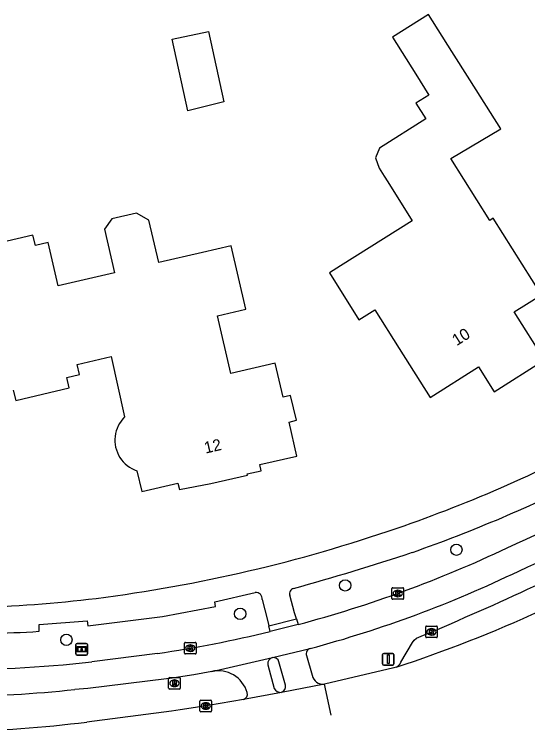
# Model space of a CAD drawing. Extents: x 161354 to 161876, y 382161 to 382804.
# Drawn here: x 161596.3 to 161640.6, y 382163 to 382224.9 of the extents above; entities that cross this region are included whole.
import ezdxf

# ---------------------------------------------------------------- set-up
doc = ezdxf.new("R2010")
doc.units = 0
for name, color, linetype in [('IMGEO_Boom', 7, 'Continuous'), ('IMGEO_Fietspad_gesloten', 7, 'Continuous'), ('IMGEO_Fietspad_open', 7, 'Continuous'), ('IMGEO_Informatiebord', 7, 'Continuous'), ('IMGEO_Kolk', 7, 'Continuous'), ('IMGEO_Pand', 7, 'Continuous'), ('IMGEO_Pand_nummerreeks', 7, 'Continuous'), ('IMGEO_Parkeervlak_gesloten', 7, 'Continuous'), ('IMGEO_Rijbaan_lokaal_gesloten', 7, 'Continuous'), ('IMGEO_Rioolput', 7, 'Continuous'), ('IMGEO_Verkeersbordpaal', 7, 'Continuous'), ('IMGEO_Voetpad_open', 7, 'Continuous')]:
    doc.layers.add(name, color=color, linetype=linetype)

msp = doc.modelspace()

# ---------------------------------------------------------------- linework, layer by layer
at = {"layer": 'IMGEO_Boom'}
for centre in [(161634.464, 382178.675), (161624.869, 382175.601), (161615.807, 382173.143), (161600.809, 382170.903)]:
    msp.add_circle(centre, 0.489, dxfattribs=at)
at = {"layer": 'IMGEO_Fietspad_gesloten'}
for points in [[(161620.807, 382172.222), (161618.406, 382171.615)], [(161618.604, 382169.368), (161621.848, 382170.151)], [(161608.671, 382169.723), (161603.005, 382168.994)], [(161613.35, 382168.179), (161618.604, 382169.368)], [(161613.35, 382168.179), (161611.805, 382167.893), (161609.731, 382167.57), (161609.449, 382167.536), (161602.674, 382166.712), (161601.532, 382166.616)]]:
    msp.add_lwpolyline(points, dxfattribs=at)
for centre, radius, start, end in [((161590.684, 382287.002), 118.402, 294.00068, 300.94195), ((161589.217, 382289.524), 123.534, 294.19262, 300.59138), ((161593.567, 382274.394), 105.741, 284.92819, 295.35244), ((161595.386, 382268.883), 102.217, 285.00366, 295.78007), ((161592.438, 382279.237), 110.71, 278.43128, 283.5654), ((161589.272, 382297.98), 129.715, 270.22249, 276.0772), ((161589.939, 382275.328), 109.328, 270.56918, 276.08702)]:
    msp.add_arc(centre, radius, start, end, dxfattribs=at)
at = {"layer": 'IMGEO_Fietspad_open'}
msp.add_lwpolyline([(161618.183, 382168.756), (161618.75, 382166.701)], dxfattribs=at)
for centre, radius, start, end in [((161618.759, 382168.811), 0.579, 105.54251, 185.40866), ((161613.898, 382165.611), 2.626, 16.30451, 102.05393), ((161615.958, 382166.226), 0.477, 284.90509, 14.88803), ((161619.281, 382166.949), 0.586, 205.02601, 278.85775)]:
    msp.add_arc(centre, radius, start, end, dxfattribs=at)
at = {"layer": 'IMGEO_Informatiebord'}
for p, q in [((161601.637, 382169.684), (161601.637, 382170.484)), ((161601.637, 382170.484), (161601.637, 382169.684)), ((161601.737, 382170.584), (161602.527, 382170.584)), ((161602.527, 382170.584), (161601.737, 382170.584)), ((161602.627, 382170.484), (161602.627, 382169.684)), ((161602.627, 382169.684), (161602.627, 382170.484)), ((161602.527, 382169.584), (161601.737, 382169.584)), ((161601.737, 382169.584), (161602.527, 382169.584))]:
    msp.add_line(p, q, dxfattribs=at)
for points in [[(161601.738, 382170.316), (161602.526, 382170.316), (161602.526, 382169.852), (161601.738, 382169.852), (161601.738, 382170.316)], [(161601.803, 382170.251), (161601.803, 382169.917), (161602.078, 382169.917), (161602.079, 382170.13), (161602.183, 382170.131), (161602.184, 382169.917), (161602.461, 382169.917), (161602.461, 382170.251), (161602.185, 382170.251), (161602.185, 382170.171), (161602.079, 382170.171), (161602.079, 382170.251), (161601.803, 382170.251)]]:
    msp.add_lwpolyline(points, dxfattribs=at)
for centre, start, end in [((161601.737, 382170.484), 90, 180), ((161601.737, 382170.484), 90, 180), ((161602.527, 382170.484), 0, 90), ((161602.527, 382170.484), 360, 90), ((161601.737, 382169.684), 180, 270), ((161601.737, 382169.684), 180, 270), ((161602.527, 382169.684), 270, 0), ((161602.527, 382169.684), 270, 0)]:
    msp.add_arc(centre, 0.1, start, end, dxfattribs=at)
at = {"layer": 'IMGEO_Kolk'}
for p, q in [((161628.909, 382174.472), (161628.909, 382175.324)), ((161628.984, 382175.398), (161629.836, 382175.398)), ((161629.397, 382175.178), (161629.422, 382175.178)), ((161629.91, 382175.324), (161629.91, 382174.472)), ((161629.836, 382174.398), (161628.984, 382174.398)), ((161629.42, 382174.618), (161629.395, 382174.618)), ((161631.816, 382171.163), (161631.816, 382172.015)), ((161631.891, 382172.089), (161632.743, 382172.089)), ((161632.304, 382171.869), (161632.329, 382171.869)), ((161632.817, 382172.015), (161632.817, 382171.163)), ((161632.327, 382171.309), (161632.302, 382171.309)), ((161611.003, 382169.754), (161611.003, 382170.606)), ((161611.078, 382170.68), (161611.93, 382170.68)), ((161612.004, 382170.606), (161612.004, 382169.754)), ((161632.743, 382171.089), (161631.891, 382171.089)), ((161611.491, 382170.46), (161611.516, 382170.46)), ((161611.93, 382169.68), (161611.078, 382169.68)), ((161611.514, 382169.9), (161611.489, 382169.9)), ((161612.415, 382165.695), (161613.267, 382165.695)), ((161612.34, 382164.769), (161612.34, 382165.621)), ((161612.828, 382165.475), (161612.853, 382165.475)), ((161613.341, 382165.621), (161613.341, 382164.769)), ((161613.267, 382164.695), (161612.415, 382164.695)), ((161612.851, 382164.915), (161612.826, 382164.915))]:
    msp.add_line(p, q, dxfattribs=at)
for points in [[(161628.909, 382174.472), (161628.909, 382175.324)], [(161628.984, 382175.398), (161629.836, 382175.398)], [(161629.23, 382175.098), (161629.353, 382175.098), (161629.353, 382174.947), (161629.483, 382175.098), (161629.647, 382175.098), (161629.501, 382174.947), (161629.654, 382174.698), (161629.502, 382174.698), (161629.417, 382174.862), (161629.353, 382174.795), (161629.353, 382174.698), (161629.23, 382174.698), (161629.23, 382175.098)], [(161629.91, 382175.324), (161629.91, 382174.472)], [(161629.836, 382174.398), (161628.984, 382174.398)], [(161631.816, 382171.163), (161631.816, 382172.015)], [(161631.891, 382172.089), (161632.743, 382172.089)], [(161632.817, 382172.015), (161632.817, 382171.163)], [(161632.137, 382171.789), (161632.26, 382171.789), (161632.26, 382171.638), (161632.39, 382171.789), (161632.554, 382171.789), (161632.408, 382171.638), (161632.561, 382171.389), (161632.409, 382171.389), (161632.324, 382171.553), (161632.26, 382171.486), (161632.26, 382171.389), (161632.137, 382171.389), (161632.137, 382171.789)], [(161611.003, 382169.754), (161611.003, 382170.606)], [(161611.078, 382170.68), (161611.93, 382170.68)], [(161612.004, 382170.606), (161612.004, 382169.754)], [(161632.743, 382171.089), (161631.891, 382171.089)], [(161611.324, 382170.38), (161611.447, 382170.38), (161611.447, 382170.229), (161611.577, 382170.38), (161611.741, 382170.38), (161611.595, 382170.229), (161611.748, 382169.98), (161611.596, 382169.98), (161611.511, 382170.144), (161611.447, 382170.077), (161611.447, 382169.98), (161611.324, 382169.98), (161611.324, 382170.38)], [(161611.93, 382169.68), (161611.078, 382169.68)], [(161612.415, 382165.695), (161613.267, 382165.695)], [(161612.34, 382164.769), (161612.34, 382165.621)], [(161612.661, 382165.395), (161612.784, 382165.395), (161612.784, 382165.244), (161612.914, 382165.395), (161613.078, 382165.395), (161612.932, 382165.244), (161613.085, 382164.995), (161612.933, 382164.995), (161612.848, 382165.159), (161612.784, 382165.092), (161612.784, 382164.995), (161612.661, 382164.995), (161612.661, 382165.395)], [(161613.341, 382165.621), (161613.341, 382164.769)], [(161613.267, 382164.695), (161612.415, 382164.695)]]:
    msp.add_lwpolyline(points, dxfattribs=at)
for centre, start, end in [((161628.986, 382175.322), 91.55205, 178.44795), ((161628.986, 382175.322), 91.55205, 178.44795), ((161629.834, 382175.322), 1.55205, 88.44795), ((161629.834, 382175.322), 1.55205, 88.44795), ((161628.986, 382174.474), 181.55205, 268.44795), ((161628.986, 382174.474), 181.55205, 268.44795), ((161629.834, 382174.474), 271.55205, 358.44795), ((161629.834, 382174.474), 271.55205, 358.44795), ((161631.893, 382172.013), 91.55205, 178.44795), ((161631.893, 382172.013), 91.55205, 178.44795), ((161632.741, 382172.013), 1.55205, 88.44795), ((161632.741, 382172.013), 1.55205, 88.44795), ((161611.08, 382170.604), 91.55205, 178.44795), ((161611.08, 382170.604), 91.55205, 178.44795), ((161611.928, 382170.604), 1.55205, 88.44795), ((161611.928, 382170.604), 1.55205, 88.44795), ((161631.893, 382171.165), 181.55205, 268.44795), ((161631.893, 382171.165), 181.55205, 268.44795), ((161632.741, 382171.165), 271.55205, 358.44795), ((161632.741, 382171.165), 271.55205, 358.44795), ((161611.08, 382169.756), 181.55205, 268.44795), ((161611.08, 382169.756), 181.55205, 268.44795), ((161611.928, 382169.756), 271.55205, 358.44795), ((161611.928, 382169.756), 271.55205, 358.44795), ((161612.417, 382165.619), 91.55205, 178.44795), ((161612.417, 382165.619), 91.55205, 178.44795), ((161613.265, 382165.619), 1.55205, 88.44795), ((161613.265, 382165.619), 1.55205, 88.44795), ((161612.417, 382164.771), 181.55205, 268.44795), ((161612.417, 382164.771), 181.55205, 268.44795), ((161613.265, 382164.771), 271.55205, 358.44795), ((161613.265, 382164.771), 271.55205, 358.44795)]:
    msp.add_arc(centre, 0.0765, start, end, dxfattribs=at)
for centre, major_axis, ratio, start_param, end_param in [((161629.396, 382174.898), (-0.387, 0.002), 0.722429, 4.712389, 7.853982), ((161629.421, 382174.898), (-0.39, 0.002), 0.717154, 1.570796, 4.712389), ((161632.303, 382171.589), (-0.387, 0.002), 0.722429, 4.712389, 7.853982), ((161632.328, 382171.589), (-0.39, 0.002), 0.717154, 1.570796, 4.712389), ((161611.49, 382170.18), (-0.387, 0.002), 0.722429, 4.712389, 7.853982), ((161611.515, 382170.18), (-0.39, 0.002), 0.717154, 1.570796, 4.712389), ((161612.827, 382165.195), (-0.387, 0.002), 0.722429, 4.712389, 7.853982), ((161612.852, 382165.195), (-0.39, 0.002), 0.717154, 1.570796, 4.712389)]:
    msp.add_ellipse(centre, major_axis=major_axis, ratio=ratio, start_param=start_param, end_param=end_param, dxfattribs=at)
at = {"layer": 'IMGEO_Pand'}
for points in [[(161628.942, 382222.91), (161630.959, 382219.713), (161632.095, 382217.912), (161630.979, 382217.209), (161631.825, 382215.867), (161627.824, 382213.343), (161627.496, 382212.485), (161627.793, 382211.616), (161628.233, 382210.919), (161628.54, 382210.432), (161630.658, 382207.071), (161624.462, 382203.164), (161623.504, 382202.56), (161626.047, 382198.524), (161627.419, 382199.389), (161629.528, 382196.042), (161632.194, 382191.812), (161636.375, 382194.447), (161637.719, 382192.315), (161642.061, 382195.052), (161639.449, 382199.198), (161641.81, 382200.686), (161637.651, 382207.285), (161637.347, 382207.094), (161633.988, 382212.424), (161638.292, 382214.996), (161635.626, 382219.226), (161634.08, 382221.68), (161632.065, 382224.878), (161628.942, 382222.91)], [(161614.403, 382217.316), (161611.289, 382216.544), (161609.951, 382222.728), (161613.088, 382223.392), (161614.403, 382217.316)], [(161608.786, 382203.456), (161607.939, 382207.103), (161606.851, 382207.729), (161604.742, 382207.239), (161604.094, 382206.33), (161604.968, 382202.569), (161600.099, 382201.437), (161599.227, 382205.183), (161598.132, 382204.93), (161597.925, 382205.82), (161593.343, 382204.755)], [(161596.222, 382192.443), (161596.46, 382191.565), (161601.044, 382192.656), (161600.854, 382193.537), (161601.938, 382193.792), (161601.732, 382194.668), (161604.666, 382195.343), (161605.838, 382190.133), (161605.674, 382189.96), (161605.526, 382189.774), (161605.394, 382189.576), (161605.28, 382189.368), (161605.183, 382189.15), (161605.106, 382188.925), (161605.048, 382188.694), (161605.011, 382188.459), (161604.993, 382188.222), (161604.996, 382187.984), (161605.019, 382187.748), (161605.062, 382187.514), (161605.125, 382187.284), (161605.208, 382187.061), (161605.309, 382186.846), (161605.428, 382186.64), (161605.565, 382186.445), (161605.717, 382186.263), (161605.885, 382186.094), (161606.067, 382185.94), (161606.261, 382185.802), (161606.466, 382185.682), (161606.68, 382185.579), (161606.903, 382185.495), (161607.313, 382183.711), (161610.442, 382184.43), (161610.584, 382183.871), (161613.271, 382184.396), (161616.449, 382185.11), (161616.423, 382185.227), (161617.622, 382185.485), (161617.507, 382186.023), (161620.702, 382186.762), (161620.024, 382189.695), (161620.662, 382189.843), (161620.162, 382191.993), (161619.523, 382191.844), (161618.84, 382194.778), (161614.994, 382193.884), (161613.837, 382198.86), (161616.299, 382199.432), (161615.026, 382204.906), (161612.565, 382204.334), (161608.786, 382203.456)]]:
    msp.add_lwpolyline(points, dxfattribs=at)
at = {"layer": 'IMGEO_Parkeervlak_gesloten'}
msp.add_lwpolyline([(161629.685, 382168.965), (161630.666, 382170.678), (161630.811, 382170.872), (161631.013, 382171.04)], dxfattribs=at)
for centre, radius, start, end in [((161577.94, 382308.949), 147.646, 295.11915, 300.38929), ((161529.493, 382414.698), 263.961, 292.6191, 294.89669), ((161628.893, 382169.328), 0.872, 294.77578, 335.35824)]:
    msp.add_arc(centre, radius, start, end, dxfattribs=at)
at = {"layer": 'IMGEO_Rijbaan_lokaal_gesloten'}
for points in [[(161629.258, 382168.537), (161629.057, 382168.471), (161623.075, 382167.083)], [(161623.075, 382167.083), (161619.371, 382166.37)], [(161623.646, 382164.414), (161623.075, 382167.083)], [(161619.371, 382166.37), (161616.081, 382165.765)], [(161616.081, 382165.765), (161613.083, 382165.226), (161610.631, 382164.856), (161609.873, 382164.757), (161602.568, 382163.808)]]:
    msp.add_lwpolyline(points, dxfattribs=at)
for centre, radius, start, end in [((161591.792, 382282.869), 120.314, 288.14375, 300.92824), ((161588.768, 382274.44), 111.489, 271.247, 277.11037)]:
    msp.add_arc(centre, radius, start, end, dxfattribs=at)
at = {"layer": 'IMGEO_Rioolput'}
for p, q in [((161609.637, 382166.731), (161609.637, 382167.583)), ((161609.712, 382167.657), (161610.564, 382167.657)), ((161610.638, 382167.583), (161610.638, 382166.731)), ((161610.148, 382166.877), (161610.123, 382166.877)), ((161610.125, 382167.437), (161610.15, 382167.437)), ((161610.564, 382166.657), (161609.712, 382166.657))]:
    msp.add_line(p, q, dxfattribs=at)
for points in [[(161609.637, 382166.731), (161609.637, 382167.583)], [(161609.712, 382167.657), (161610.564, 382167.657)], [(161610.638, 382167.583), (161610.638, 382166.731)], [(161610.226, 382167.355), (161609.974, 382167.357), (161609.974, 382166.957)], [(161609.974, 382166.957), (161610.098, 382166.957), (161610.098, 382167.119), (161610.109, 382167.119)], [(161610.152, 382167.276), (161610.098, 382167.276), (161610.098, 382167.195)], [(161610.098, 382167.195), (161610.15, 382167.195)], [(161610.156, 382167.09), (161610.227, 382166.957), (161610.367, 382166.957), (161610.302, 382167.083)], [(161610.564, 382166.657), (161609.712, 382166.657)]]:
    msp.add_lwpolyline(points, dxfattribs=at)
for centre, radius, start, end in [((161609.714, 382167.581), 0.0765, 91.55205, 178.44795), ((161609.714, 382167.581), 0.0765, 91.55205, 178.44795), ((161610.562, 382167.581), 0.0765, 1.55205, 88.44795), ((161610.562, 382167.581), 0.0765, 1.55205, 88.44795), ((161610.108, 382167.066), 0.0533, 26.02933, 88.69889), ((161610.134, 382167.384), 0.19, 274.7715, 282.96867), ((161610.158, 382167.18), 0.0964, 77.00612, 93.18647), ((161610.172, 382167.237), 0.0378, 276.66336, 79.67722), ((161610.225, 382167.245), 0.109, 350.36119, 89.41601), ((161610.223, 382167.245), 0.112, 277.58423, 350.98172), ((161610.207, 382167.03), 0.108, 29.51342, 73.79051), ((161609.714, 382166.733), 0.0765, 181.55205, 268.44795), ((161609.714, 382166.733), 0.0765, 181.55205, 268.44795), ((161610.562, 382166.733), 0.0765, 271.55205, 358.44795), ((161610.562, 382166.733), 0.0765, 271.55205, 358.44795)]:
    msp.add_arc(centre, radius, start, end, dxfattribs=at)
for centre, major_axis, ratio, start_param, end_param in [((161610.124, 382167.157), (-0.387, 0.002), 0.722429, 4.712389, 7.853982), ((161610.149, 382167.157), (-0.39, 0.002), 0.717154, 1.570796, 4.712389)]:
    msp.add_ellipse(centre, major_axis=major_axis, ratio=ratio, start_param=start_param, end_param=end_param, dxfattribs=at)
at = {"layer": 'IMGEO_Verkeersbordpaal'}
for p, q in [((161628.091, 382168.826), (161628.091, 382169.626)), ((161628.091, 382169.626), (161628.091, 382168.826)), ((161628.191, 382169.726), (161628.981, 382169.726)), ((161628.981, 382169.726), (161628.191, 382169.726)), ((161629.081, 382169.626), (161629.081, 382168.826)), ((161629.081, 382168.826), (161629.081, 382169.626)), ((161628.981, 382168.726), (161628.191, 382168.726)), ((161628.191, 382168.726), (161628.981, 382168.726))]:
    msp.add_line(p, q, dxfattribs=at)
msp.add_lwpolyline([(161628.511, 382169.601), (161628.661, 382169.601), (161628.661, 382168.851), (161628.511, 382168.851), (161628.511, 382169.601)], dxfattribs=at)
for centre, start, end in [((161628.191, 382169.626), 90, 180), ((161628.191, 382169.626), 90, 180), ((161628.981, 382169.626), 0, 90), ((161628.981, 382169.626), 360, 90), ((161628.191, 382168.826), 180, 270), ((161628.191, 382168.826), 180, 270), ((161628.981, 382168.826), 270, 0), ((161628.981, 382168.826), 270, 0)]:
    msp.add_arc(centre, 0.1, start, end, dxfattribs=at)
at = {"layer": 'IMGEO_Voetpad_open'}
for points in [[(161598.464, 382171.635), (161598.451, 382172.225), (161602.604, 382172.529), (161602.651, 382172.104), (161609.108, 382172.914), (161613.676, 382173.763), (161613.609, 382174.191), (161617.105, 382174.992)], [(161617.707, 382174.377), (161618.164, 382172.606), (161618.287, 382172.101)], [(161620.665, 382172.701), (161620.507, 382173.236), (161620.079, 382174.76)], [(161618.287, 382172.101), (161620.665, 382172.701)], [(161620.665, 382172.701), (161620.807, 382172.222)], [(161618.406, 382171.615), (161618.287, 382172.101)], [(161621.537, 382169.542), (161622.017, 382167.838)], [(161619.713, 382166.991), (161619.158, 382169.001)]]:
    msp.add_lwpolyline(points, dxfattribs=at)
for centre, radius, start, end in [((161590.072, 382294.659), 120.691, 288.99579, 298.7071), ((161587.822, 382300.35), 129.214, 289.37205, 296.70653), ((161586.822, 382304.086), 130.662, 277.28589, 288.99778), ((161562.805, 382383.567), 216.054, 285.46187, 288.31062), ((161617.156, 382174.44), 0.555, 353.50245, 95.27353), ((161620.524, 382174.886), 0.462, 105.02708, 195.76402), ((161589.019, 382294.335), 120.715, 266.67804, 276.83867), ((161588.636, 382338.202), 166.857, 270.3804, 273.37665), ((161621.961, 382169.71), 0.456, 104.30799, 201.58765), ((161618.672, 382168.869), 0.503, 15.17649, 97.77816), ((161622.964, 382168.047), 0.97, 192.42527, 276.55062), ((161619.196, 382166.871), 0.53, 289.22332, 13.09136)]:
    msp.add_arc(centre, radius, start, end, dxfattribs=at)

# ---------------------------------------------------------------- texts
at = {"layer": 'IMGEO_Pand_nummerreeks'}
for s, rotation, p in [('10', 32.22315, (161634.494, 382196.239)), ('12', 12.91447, (161612.821, 382186.969))]:
    msp.add_text(s, height=1, rotation=rotation, dxfattribs=at).set_placement(p)

doc.saveas('drawing.dxf')
